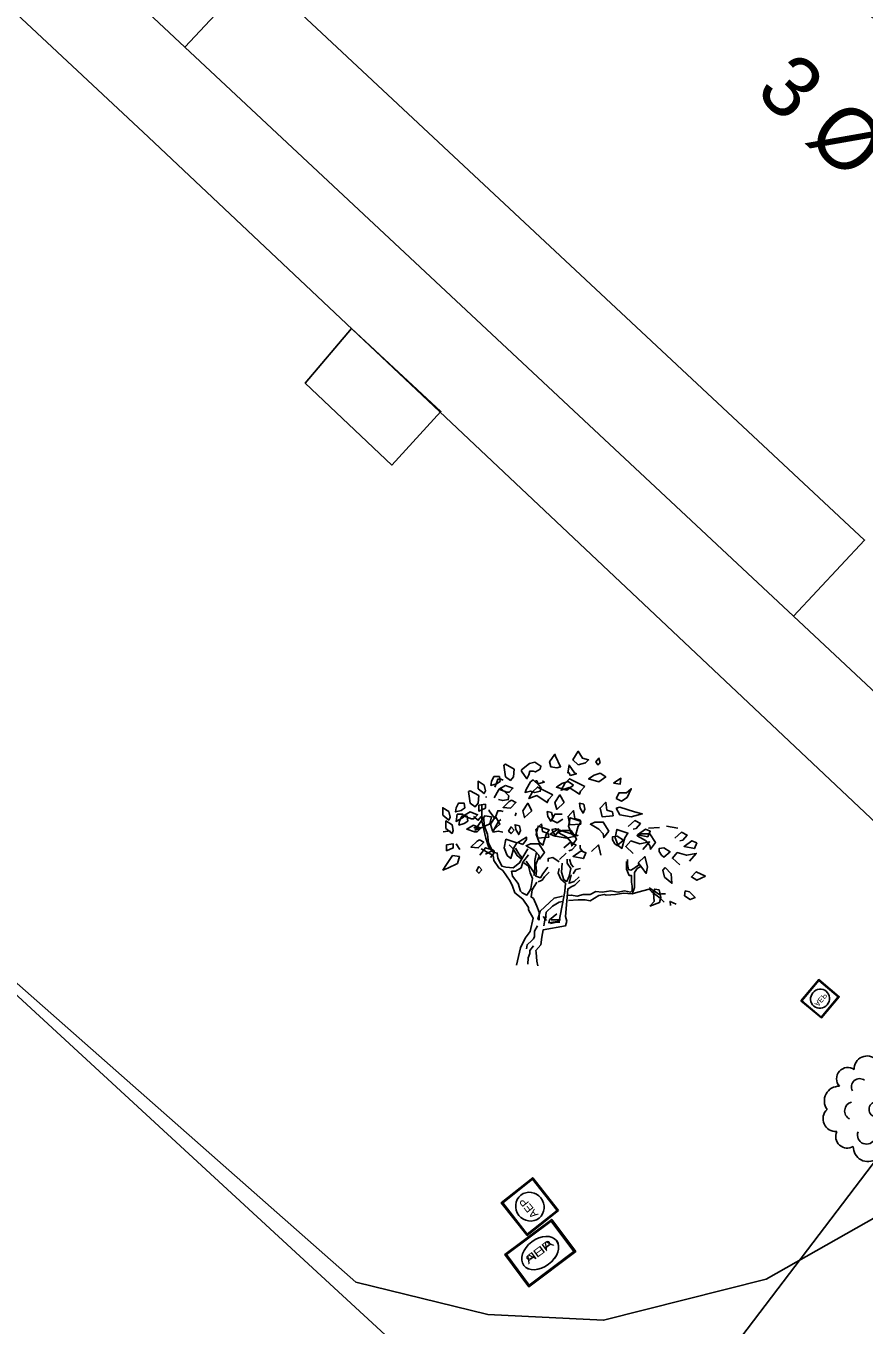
# Model space of a CAD drawing. Extents: x 343997 to 344255, y 298512 to 298767.
# Drawn here: x 344151.36 to 344165.08, y 298671.53 to 298692.79 of the extents above; entities that cross this region are included whole.
import ezdxf

# ---------------------------------------------------------------- set-up
doc = ezdxf.new("R2010")
doc.units = 0
for name, color, linetype in [('Default', 7, 'Continuous'), ('DH_CADRE-CARTOUCHE', 7, 'Continuous'), ('DIR-Projet VRD1', 7, 'Continuous'), ('GO_DALLE', 7, 'Continuous'), ('OPT texte', 7, 'Continuous'), ('OPT VRD', 7, 'Continuous'), ('PC_REBAR', 7, 'Continuous'), ('PS_MID', 7, 'Continuous'), ('PS_PLATE', 7, 'Continuous'), ('RES_EAU', 7, 'Continuous')]:
    doc.layers.add(name, color=color, linetype=linetype)

# ---------------------------------------------------------------- blocks, each defined once
blk = doc.blocks.new('RES_EAU')
at = {"layer": 'RES_EAU'}
for points in [[(0, 0), (0, 0.1), (0.1, 0.1), (0.1, 0)], [(0.0025, 0.0025), (0.0025, 0.0975), (0.0975, 0.0975), (0.0975, 0.0025)]]:
    blk.add_lwpolyline(points, close=True, dxfattribs=at)
blk.add_circle((0.05, 0.05), 0.035, dxfattribs=at)
blk.add_text('AEP', height=0.02, dxfattribs=at).set_placement((0.0224, 0.0448))
blk = doc.blocks.new('ARB1')
at = {"layer": 'Default'}
blk.add_circle((0, 0), 0.0122, dxfattribs=at)
for centre, radius, start, end in [((-0.0153, 0.0664), 0.0211, 43.6925, 183.5969), ((0.0139, 0.0613), 0.0241, 358.4583, 125.1928), ((-0.0471, 0.0503), 0.0183, 53.9554, 222.2066), ((0.0501, 0.0468), 0.0183, 325.1444, 131.0175), ((-0.0276, 0.037), 0.0134, 52.4396, 209.5496), ((0.0164, 0.038), 0.0112, 330.5895, 133.7127), ((-0.0613, 0.0139), 0.0241, 88.4583, 215.1928), ((0.0664, 0.0153), 0.0211, 313.6925, 93.5969), ((-0.0373, -0.0024), 0.0149, 103.7092, 242.3465), ((0.0458, 0.0052), 0.0137, 276.6214, 88.967), ((0.0613, -0.0139), 0.0241, 268.4583, 35.1928), ((-0.0664, -0.0153), 0.0211, 133.6925, 273.5969), ((-0.0478, -0.0443), 0.019, 155.2243, 300.9377), ((-0.0163, -0.042), 0.0148, 159.5371, 338.1663), ((0.0271, -0.038), 0.0112, 210.5895, 13.7127), ((0.0448, -0.0483), 0.0188, 243.1323, 33.0297), ((-0.0139, -0.0613), 0.0241, 178.4583, 305.1928), ((0.0153, -0.0664), 0.0211, 223.6925, 3.5969)]:
    blk.add_arc(centre, radius, start, end, dxfattribs=at)
blk = doc.blocks.new('FLAMBOY')
at = {"layer": 'Default'}
for p, q in [((-0.0832, 0.3464), (-0.0832, 0.3442)), ((-0.0238, 0.3069), (-0.0213, 0.3132)), ((-0.157, 0.2764), (-0.1707, 0.2742)), ((0.2497, 0.2813), (0.2722, 0.2832)), ((0.3097, 0.2813), (0.2859, 0.2854)), ((-0.1371, 0.2378), (-0.1446, 0.2497)), ((0.0808, 0.2303), (0.0671, 0.2171)), ((0.0866, 0.1688), (0.0866, 0.1688)), ((0.0407, 0.0927), (0.0337, 0.1011))]:
    blk.add_line(p, q, dxfattribs=at)
for points in [[(0.0617, 0.4053), (0.0692, 0.4072), (0.0592, 0.4288), (0.0579, 0.4328), (0.0467, 0.4172), (0.0492, 0.4072)], [(0.1054, 0.4113), (0.1204, 0.415), (0.1267, 0.4213), (0.1142, 0.425), (0.1054, 0.4388), (0.0942, 0.4213)], [(-0.0471, 0.4106), (-0.0433, 0.3866), (-0.0333, 0.3791), (-0.0271, 0.3866), (-0.0258, 0.4025), (-0.0433, 0.4122)], [(0.0054, 0.4141), (-0.0108, 0.4006), (-0.0108, 0.3985), (0.0004, 0.3825), (0.0042, 0.3906), (0.0067, 0.3985), (0.0129, 0.3985), (0.0179, 0.3966), (0.0279, 0.4025), (0.0292, 0.4085), (0.0167, 0.4163)], [(0.0892, 0.3891), (0.0867, 0.395), (0.0842, 0.395), (0.0867, 0.4106), (0.0979, 0.395), (0.1017, 0.3928)], [(0.1504, 0.415), (0.1479, 0.425), (0.1417, 0.4172), (0.1454, 0.4113)], [(-0.0846, 0.3581), (-0.0871, 0.3697), (-0.0996, 0.3775), (-0.0996, 0.3622), (-0.0871, 0.3522)], [(-0.0621, 0.3722), (-0.0546, 0.3772), (-0.0558, 0.3872), (-0.0671, 0.3872), (-0.0721, 0.3772), (-0.0733, 0.3691)], [(0.0292, 0.3644), (0.0254, 0.3685), (0.0129, 0.3803), (0.0079, 0.3763), (-0.0008, 0.3606), (-0.0033, 0.3547), (0.0079, 0.3569), (0.0167, 0.3547), (0.0279, 0.3569)], [(0.0958, 0.3693), (0.0821, 0.3593), (0.0608, 0.3653), (0.0721, 0.3731), (0.0846, 0.3768)], [(0.1192, 0.3669), (0.1029, 0.375), (0.0879, 0.3825), (0.0779, 0.3731), (0.0704, 0.3591), (0.0867, 0.365), (0.1079, 0.351), (0.1104, 0.3572)], [(0.1504, 0.3938), (0.1617, 0.3863), (0.1479, 0.3763), (0.1267, 0.3822), (0.1379, 0.39)], [(0.1779, 0.3738), (0.1917, 0.3716), (0.1929, 0.3838)], [(-0.1195, 0.3564), (-0.1157, 0.3324), (-0.1057, 0.3249), (-0.0995, 0.3324), (-0.0982, 0.3483), (-0.1157, 0.358)], [(-0.0433, 0.3691), (-0.0571, 0.361), (-0.0408, 0.355), (-0.0358, 0.355), (-0.0283, 0.3631)], [(0.0533, 0.35), (0.0371, 0.3581), (0.0221, 0.3656), (0.0121, 0.3562), (0.0046, 0.3421), (0.0208, 0.3481), (0.0421, 0.334), (0.0446, 0.3403)], [(0.0767, 0.3338), (0.0679, 0.3494), (0.0579, 0.3338), (0.0617, 0.32)], [(0.1829, 0.3422), (0.1892, 0.3541), (0.2042, 0.3541), (0.2142, 0.3622), (0.2054, 0.3441), (0.1942, 0.3366)], [(-0.172, 0.308), (-0.1595, 0.298), (-0.157, 0.3039), (-0.1595, 0.3155), (-0.172, 0.3233)], [(-0.1345, 0.318), (-0.127, 0.323), (-0.1282, 0.333), (-0.1395, 0.333), (-0.1445, 0.323), (-0.1457, 0.3149)], [(-0.0983, 0.3285), (-0.0983, 0.3166), (-0.0846, 0.3225), (-0.0846, 0.3306)], [(-0.0308, 0.3388), (-0.0358, 0.336), (-0.0483, 0.3241), (-0.0333, 0.3225), (-0.0221, 0.3341)], [(0.0108, 0.3168), (0.0021, 0.3325), (-0.0079, 0.3168), (-0.0042, 0.3031)], [(0.1167, 0.3306), (0.1079, 0.3325), (0.1092, 0.3225), (0.1154, 0.3125), (0.1192, 0.3206)], [(0.1767, 0.3069), (0.1754, 0.3147), (0.1642, 0.3185), (0.1617, 0.3344), (0.1504, 0.3225), (0.1542, 0.305)], [(0.1829, 0.3225), (0.1904, 0.3244), (0.2204, 0.3147), (0.2367, 0.3106), (0.2142, 0.305), (0.1904, 0.3091)], [(-0.1504, 0.2768), (-0.1529, 0.2884), (-0.1654, 0.2962), (-0.1654, 0.2809), (-0.1529, 0.2709)], [(-0.1421, 0.3103), (-0.1308, 0.3103), (-0.1296, 0.3038), (-0.1446, 0.2953)], [(-0.1392, 0.2878), (-0.1279, 0.2909), (-0.1204, 0.2959), (-0.1217, 0.3059), (-0.1329, 0.3059), (-0.1379, 0.2959)], [(-0.1132, 0.3008), (-0.1082, 0.3008), (-0.1007, 0.3089), (-0.1157, 0.3149), (-0.1295, 0.3067)], [(-0.0958, 0.281), (-0.0758, 0.2906), (-0.0721, 0.3047), (-0.0858, 0.3066), (-0.0983, 0.2888), (-0.1058, 0.2772)], [(-0.07, 0.276), (-0.055, 0.2897), (-0.0638, 0.3053), (-0.0738, 0.2897)], [(0.0508, 0.3137), (0.0421, 0.3156), (0.0433, 0.3056), (0.0496, 0.2956), (0.0533, 0.3037)], [(0.1108, 0.29), (0.1096, 0.2978), (0.0983, 0.3015), (0.0958, 0.3175), (0.0846, 0.3056), (0.0883, 0.2881)], [(0.1117, 0.2953), (0.1054, 0.2853), (0.0992, 0.2638), (0.0917, 0.2697), (0.0854, 0.2853), (0.0892, 0.3028)], [(0.1679, 0.2756), (0.1567, 0.2938), (0.1392, 0.2938), (0.1304, 0.2897), (0.1479, 0.2797), (0.1567, 0.27), (0.1579, 0.2622)], [(-0.1092, 0.2878), (-0.1229, 0.2796), (-0.1067, 0.2737), (-0.1017, 0.2737), (-0.0942, 0.2818)], [(-0.0258, 0.2775), (-0.0321, 0.2841), (-0.0371, 0.2756), (-0.0321, 0.2706)], [(-0.015, 0.2866), (-0.0238, 0.2885), (-0.0225, 0.2785), (-0.0163, 0.2685), (-0.0125, 0.2766)], [(0.03, 0.2903), (0.0187, 0.2785), (0.0225, 0.261), (0.045, 0.2628), (0.0437, 0.2707), (0.0325, 0.2744)], [(0.0396, 0.2684), (0.0458, 0.2784), (0.0233, 0.2859), (0.0196, 0.2684), (0.0258, 0.2528), (0.0333, 0.2468)], [(0.0579, 0.2653), (0.0654, 0.2753), (0.0654, 0.28), (0.0479, 0.2694)], [(0.0512, 0.2785), (0.0587, 0.2803), (0.0887, 0.2707), (0.105, 0.2666), (0.0825, 0.261), (0.0587, 0.265)], [(0.0733, 0.2768), (0.0646, 0.2728), (0.0821, 0.2628), (0.0908, 0.2531), (0.0921, 0.2453), (0.1021, 0.2587), (0.0908, 0.2768)], [(0.2009, 0.2616), (0.2072, 0.2716), (0.1847, 0.2791), (0.1809, 0.2616), (0.1872, 0.246), (0.1947, 0.24)], [(0.2522, 0.27), (0.2347, 0.27), (0.2259, 0.266), (0.2434, 0.256), (0.2522, 0.2463), (0.2534, 0.2385), (0.2634, 0.2519)], [(0.2479, 0.2635), (0.2267, 0.2678), (0.2429, 0.2794), (0.2529, 0.2753)], [(-0.1642, 0.2471), (-0.1642, 0.2353), (-0.1504, 0.2412), (-0.1504, 0.2493)], [(-0.0967, 0.2574), (-0.1017, 0.2546), (-0.1142, 0.2428), (-0.0992, 0.2412), (-0.0879, 0.2528)], [(-0.0263, 0.2413), (-0.02, 0.2513), (-0.0425, 0.2588), (-0.0463, 0.2413), (-0.04, 0.2257), (-0.0325, 0.2197)], [(-0.0079, 0.2484), (-0.0179, 0.2525), (-0.0004, 0.2631), (-0.0004, 0.2584)], [(0.0075, 0.2497), (-0.0013, 0.2457), (0.0162, 0.2357), (0.025, 0.226), (0.0262, 0.2182), (0.0362, 0.2316), (0.025, 0.2497)], [(0.1804, 0.2497), (0.1854, 0.246), (0.1979, 0.2569), (0.1854, 0.2653), (0.1754, 0.2635), (0.1754, 0.2575)], [(0.2759, 0.226), (0.2809, 0.2222), (0.2934, 0.2332), (0.2809, 0.2416), (0.2709, 0.2397), (0.2709, 0.2338)], [(0.3484, 0.2516), (0.3434, 0.2397), (0.3222, 0.2441), (0.3384, 0.2557)], [(-0.1617, 0.1996), (-0.1417, 0.2093), (-0.1379, 0.2234), (-0.1517, 0.2253), (-0.1642, 0.2074), (-0.1717, 0.1959)], [(0.1112, 0.2353), (0.1212, 0.2313), (0.1162, 0.2194), (0.095, 0.2238)], [(0.2284, 0.2104), (0.2359, 0.2007), (0.2447, 0.1888), (0.2472, 0.2025), (0.2422, 0.2235)], [(-0.0917, 0.1962), (-0.0979, 0.2028), (-0.1029, 0.1943), (-0.0979, 0.1893)], [(0.2834, 0.201), (0.2784, 0.1957), (0.2822, 0.1813), (0.2972, 0.1688), (0.2959, 0.1882)], [(0.3659, 0.1835), (0.3472, 0.1925), (0.3372, 0.1819), (0.3484, 0.175)], [(0.2522, 0.1216), (0.2722, 0.1294), (0.2747, 0.1394), (0.2709, 0.155), (0.2622, 0.1569), (0.2597, 0.1491), (0.2609, 0.1316)], [(0.3334, 0.151), (0.3247, 0.1532), (0.3234, 0.1432), (0.3347, 0.1354), (0.3447, 0.1394)]]:
    blk.add_lwpolyline(points, close=True, dxfattribs=at)
for points in [[(-0.0654, 0.3656), (-0.0617, 0.3737), (-0.0592, 0.3815), (-0.0529, 0.3815), (-0.0479, 0.3796)], [(0.0321, 0.3781), (0.0358, 0.3759), (0.0233, 0.3721), (0.0208, 0.3781), (0.0183, 0.3781)], [(-0.0579, 0.34), (-0.0492, 0.3378), (-0.0379, 0.34), (-0.0367, 0.3475), (-0.0404, 0.3515), (-0.0529, 0.3634), (-0.0579, 0.3593), (-0.0667, 0.3437)], [(-0.0719, 0.2357), (-0.0785, 0.2441), (-0.0834, 0.261), (-0.0916, 0.2965), (-0.0916, 0.315), (-0.0916, 0.3302)], [(-0.0767, 0.3193), (-0.0767, 0.3171), (-0.0654, 0.3012), (-0.0617, 0.3093), (-0.0592, 0.3171), (-0.0529, 0.3171), (-0.0479, 0.3153)], [(-0.1092, 0.3053), (-0.0992, 0.2978), (-0.0929, 0.3053)], [(-0.0883, 0.3049), (-0.0867, 0.2846), (-0.0801, 0.2694), (-0.0785, 0.2509), (-0.0686, 0.2323), (-0.0604, 0.2306), (-0.0588, 0.2205), (-0.0506, 0.2036), (-0.0424, 0.2019), (-0.0276, 0.2002), (-0.0145, 0.2103), (-0.0079, 0.2221), (0.002, 0.239)], [(-0.0529, 0.299), (-0.0579, 0.2949), (-0.0667, 0.2793), (-0.0692, 0.2734), (-0.0579, 0.2756), (-0.0492, 0.2734)], [(0.0737, 0.3), (0.0625, 0.2925), (0.0512, 0.2982), (0.0575, 0.31), (0.0725, 0.31)], [(0.2079, 0.285), (0.2217, 0.2969), (0.2329, 0.291), (0.2242, 0.281), (0.2179, 0.2794)], [(-0.0945, 0.2799), (-0.1032, 0.2846), (-0.1082, 0.2817)], [(0.3134, 0.2557), (0.3197, 0.2572), (0.3284, 0.2672), (0.3172, 0.2732), (0.3034, 0.2613)], [(-0.0846, 0.2281), (-0.0683, 0.2363), (-0.0846, 0.2413), (-0.0958, 0.2266)], [(-0.0112, 0.2188), (-0.0194, 0.2255), (-0.0276, 0.239), (-0.0358, 0.2475)], [(-0.0227, 0.2407), (-0.0161, 0.2289), (-0.0095, 0.2205)], [(0.0862, 0.2353), (0.0925, 0.2369), (0.1012, 0.2469), (0.09, 0.2528), (0.0762, 0.241)], [(0.1096, 0.2465), (0.1096, 0.2406), (0.1146, 0.2328)], [(0.1517, 0.2263), (0.1467, 0.2472), (0.1329, 0.2341)], [(0.2179, 0.23), (0.2029, 0.2438), (0.2129, 0.2553), (0.2317, 0.2497), (0.2517, 0.2535), (0.2379, 0.2378)], [(-0.021, 0.0009), (-0.0128, 0.0364), (-0.003, 0.0566), (0.0069, 0.0701), (0.0134, 0.0972), (0.0036, 0.1141), (0.0036, 0.1191), (-0.0079, 0.136), (-0.0243, 0.1495), (-0.0292, 0.163), (-0.0341, 0.1732), (-0.0489, 0.1951), (-0.0571, 0.2002), (-0.067, 0.2154), (-0.0686, 0.2255), (-0.0932, 0.239)], [(-0.0663, 0.236), (-0.0663, 0.2313), (-0.0738, 0.2213)], [(0.0036, 0.2272), (-0.0079, 0.212), (-0.0112, 0.2002), (-0.0227, 0.1934), (-0.0309, 0.1934), (-0.0292, 0.1833), (-0.0177, 0.1681), (-0.0128, 0.1529), (-0.0095, 0.1495), (0.0003, 0.1445), (0.0069, 0.1546), (0.0085, 0.158), (0.0118, 0.1782), (0.0069, 0.1901), (0.0036, 0.2036), (-0.0062, 0.2103)], [(-0.0013, 0.2137), (0.0085, 0.2002), (0.0151, 0.1901), (0.0151, 0.185), (0.0167, 0.2002), (0.0167, 0.2154), (0.02, 0.2323)], [(0.0249, 0.2221), (0.0184, 0.2069), (0.02, 0.1934), (0.0184, 0.1833), (0.0282, 0.1799), (0.0331, 0.1884), (0.043, 0.2019)], [(0.0662, 0.2128), (0.0537, 0.2213), (0.0437, 0.2194), (0.0437, 0.2135)], [(0.0725, 0.2099), (0.0713, 0.1918), (0.076, 0.1761), (0.0819, 0.1724), (0.0866, 0.1833), (0.0901, 0.199), (0.083, 0.2099), (0.083, 0.2184)], [(0.204, 0.2135), (0.204, 0.1978), (0.2099, 0.1845), (0.2146, 0.1845), (0.2146, 0.1712), (0.2157, 0.1628), (0.2157, 0.1543), (0.2122, 0.1507), (0.2005, 0.1531), (0.1876, 0.1507), (0.1723, 0.1531), (0.1547, 0.1507), (0.1418, 0.1519), (0.13, 0.1459), (0.1159, 0.1459), (0.103, 0.1422), (0.0912, 0.1446), (0.0819, 0.1434)], [(0.0877, 0.2184), (0.0912, 0.2075), (0.0959, 0.2015)], [(0.2298, 0.2063), (0.2193, 0.199), (0.2134, 0.1954), (0.2087, 0.1966), (0.2063, 0.2075), (0.2063, 0.2172)], [(0.3134, 0.2063), (0.2984, 0.22), (0.3084, 0.2316), (0.3272, 0.226), (0.3472, 0.2297), (0.3334, 0.2141)], [(0.0463, 0.1917), (0.0364, 0.1816), (0.0315, 0.1749), (0.0233, 0.1715)], [(0.0619, 0.106), (0.0466, 0.0939), (0.0454, 0.0878), (0.0666, 0.0915), (0.0783, 0.1519), (0.0795, 0.1688), (0.0701, 0.1773), (0.0642, 0.1894), (0.0666, 0.199)], [(0.0948, 0.1882), (0.1006, 0.1966), (0.11, 0.199)], [(0.2169, 0.1483), (0.2204, 0.1604), (0.2204, 0.1797), (0.2204, 0.1906), (0.2263, 0.199), (0.2345, 0.2039)], [(0.0208, 0.1712), (0.0114, 0.1555), (0.009, 0.141), (0.0137, 0.1374), (0.0208, 0.1217), (0.0255, 0.1096), (0.0255, 0.0939), (0.0231, 0.0951), (0.0278, 0.112), (0.056, 0.1386), (0.0736, 0.1422)], [(0.1089, 0.1749), (0.0983, 0.1652), (0.0912, 0.1616), (0.0842, 0.1567), (0.0795, 0.1011), (0.0819, 0.0915), (0.0795, 0.0818), (0.0337, 0.0733), (0.0313, 0.0588), (0.029, 0.0431), (0.0184, 0.031), (0.0196, 0.0274), (0.0208, 0.0093), (0.0231, -0.0001)], [(0.0912, 0.1857), (0.0866, 0.1688), (0.0971, 0.1724), (0.1077, 0.1821)], [(0.0854, 0.1338), (0.1053, 0.135), (0.1194, 0.135), (0.13, 0.1326), (0.1476, 0.1434), (0.1594, 0.1459), (0.1629, 0.1446), (0.1817, 0.1459), (0.1981, 0.1483), (0.2157, 0.1471), (0.2275, 0.1507), (0.251, 0.1567), (0.2557, 0.1519), (0.2733, 0.1386), (0.2815, 0.1301)], [(0.251, 0.1592), (0.2721, 0.1459), (0.2768, 0.1471), (0.2803, 0.1471), (0.2839, 0.1471)], [(0.0384, 0.0975), (0.0396, 0.1096), (0.0525, 0.1217), (0.0666, 0.1301), (0.0736, 0.1314)], [(0.3059, 0.1257), (0.2934, 0.1316), (0.2947, 0.1235)], [(0.022, 0.0818), (0.0161, 0.0709), (0.0161, 0.06), (0.0137, 0.0552), (0.0102, 0.0516), (0.0008, 0.0431), (-0.0004, 0.0347)], [(0.0349, 0.0818), (0.0372, 0.0939), (0.0396, 0.1011)], [(0.049, 0.0866), (0.0619, 0.0891), (0.0678, 0.0891)], [(0.0501, 0.0939), (0.0607, 0.0939), (0.0689, 0.0939)], [(0.0137, 0.0407), (0.0067, 0.031), (0.0067, 0.025), (0.0032, 0.0165), (0.002, 0.0032)]]:
    blk.add_lwpolyline(points, dxfattribs=at)

msp = doc.modelspace()

# ---------------------------------------------------------------- linework, layer by layer
at = {"layer": 'DH_CADRE-CARTOUCHE'}
msp.add_lwpolyline([(344122.649, 298749.916), (344119.175, 298746.216), (344104.333, 298729.921), (344103.629, 298728.425), (344103.178, 298726.908), (344102.994, 298725.349), (344103.009, 298724.152), (344103.293, 298722.366), (344103.622, 298721.156), (344104.336, 298719.642), (344105.154, 298718.475), (344128.542, 298697.099), (344156.76, 298672.229), (344158.923, 298671.699), (344160.816, 298671.605), (344163.478, 298672.279), (344165.611, 298673.484), (344167.1, 298674.65), (344168.229, 298675.97), (344184.084, 298692.584)], dxfattribs=at)
at = {"layer": 'DIR-Projet VRD1'}
msp.add_line((344129.041, 298697.326), (344161.307, 298667.622), dxfattribs=at)
at = {"layer": 'GO_DALLE'}
msp.add_lwpolyline([(344165.544, 298681.621), (344165.531, 298681.558), (344168.3, 298678.926), (344167.289, 298677.848), (344153.365, 298690.972), (344139.141, 298704.253), (344140.184, 298705.334)], dxfattribs=at)
msp.add_lwpolyline([(344156.685, 298687.841), (344155.93, 298686.947), (344157.346, 298685.603), (344158.152, 298686.481)], close=True, dxfattribs=at)
at = {"layer": 'OPT VRD'}
msp.add_lwpolyline([(344171.755, 298682.743), (344159.176, 298666.214)], dxfattribs=at)
at = {"layer": 'PS_MID'}
msp.add_lwpolyline([(344163.929, 298683.13), (344153.96, 298692.447)], dxfattribs=at)
at = {"layer": 'PS_PLATE'}
msp.add_lwpolyline([(344163.929, 298683.13), (344165.092, 298684.375), (344155.123, 298693.692), (344153.96, 298692.447), (344140.184, 298705.334), (344145.624, 298711.233), (344171.024, 298687.508), (344165.544, 298681.621)], close=True, dxfattribs=at)

# ---------------------------------------------------------------- block references
at = {"layer": 'PC_REBAR'}
for name, p, xscale, yscale in [('FLAMBOY', (344159.557, 298677.408), 8, 8), ('ARB1', (344165.286, 298675.056), 10, 10)]:
    msp.add_blockref(name, p, dxfattribs=dict(at, xscale=xscale, yscale=yscale))
at = {"layer": 'RES_EAU'}
for p, xscale, yscale, rotation in [((344164.048, 298676.834), 4.549006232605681, -4.374859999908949, 49.95332999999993), ((344160.08, 298673.399), 6.8476567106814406, 6.56658095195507, 128.32316999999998), ((344160.359, 298672.73), 9.614295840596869, -6.552410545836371, -143.18136000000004), ((344159.59, 298672.154), 9.614295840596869, 6.552410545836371, 36.81863999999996)]:
    msp.add_blockref('RES_EAU', p, dxfattribs=dict(at, xscale=xscale, yscale=yscale, rotation=rotation))

# ---------------------------------------------------------------- texts
at = {"layer": 'OPT texte'}
msp.add_text('3 Ø 45 OPT', height=1.0003, rotation=317.3672, dxfattribs=at).set_placement((344163.278, 298691.686))

doc.saveas('drawing.dxf')
